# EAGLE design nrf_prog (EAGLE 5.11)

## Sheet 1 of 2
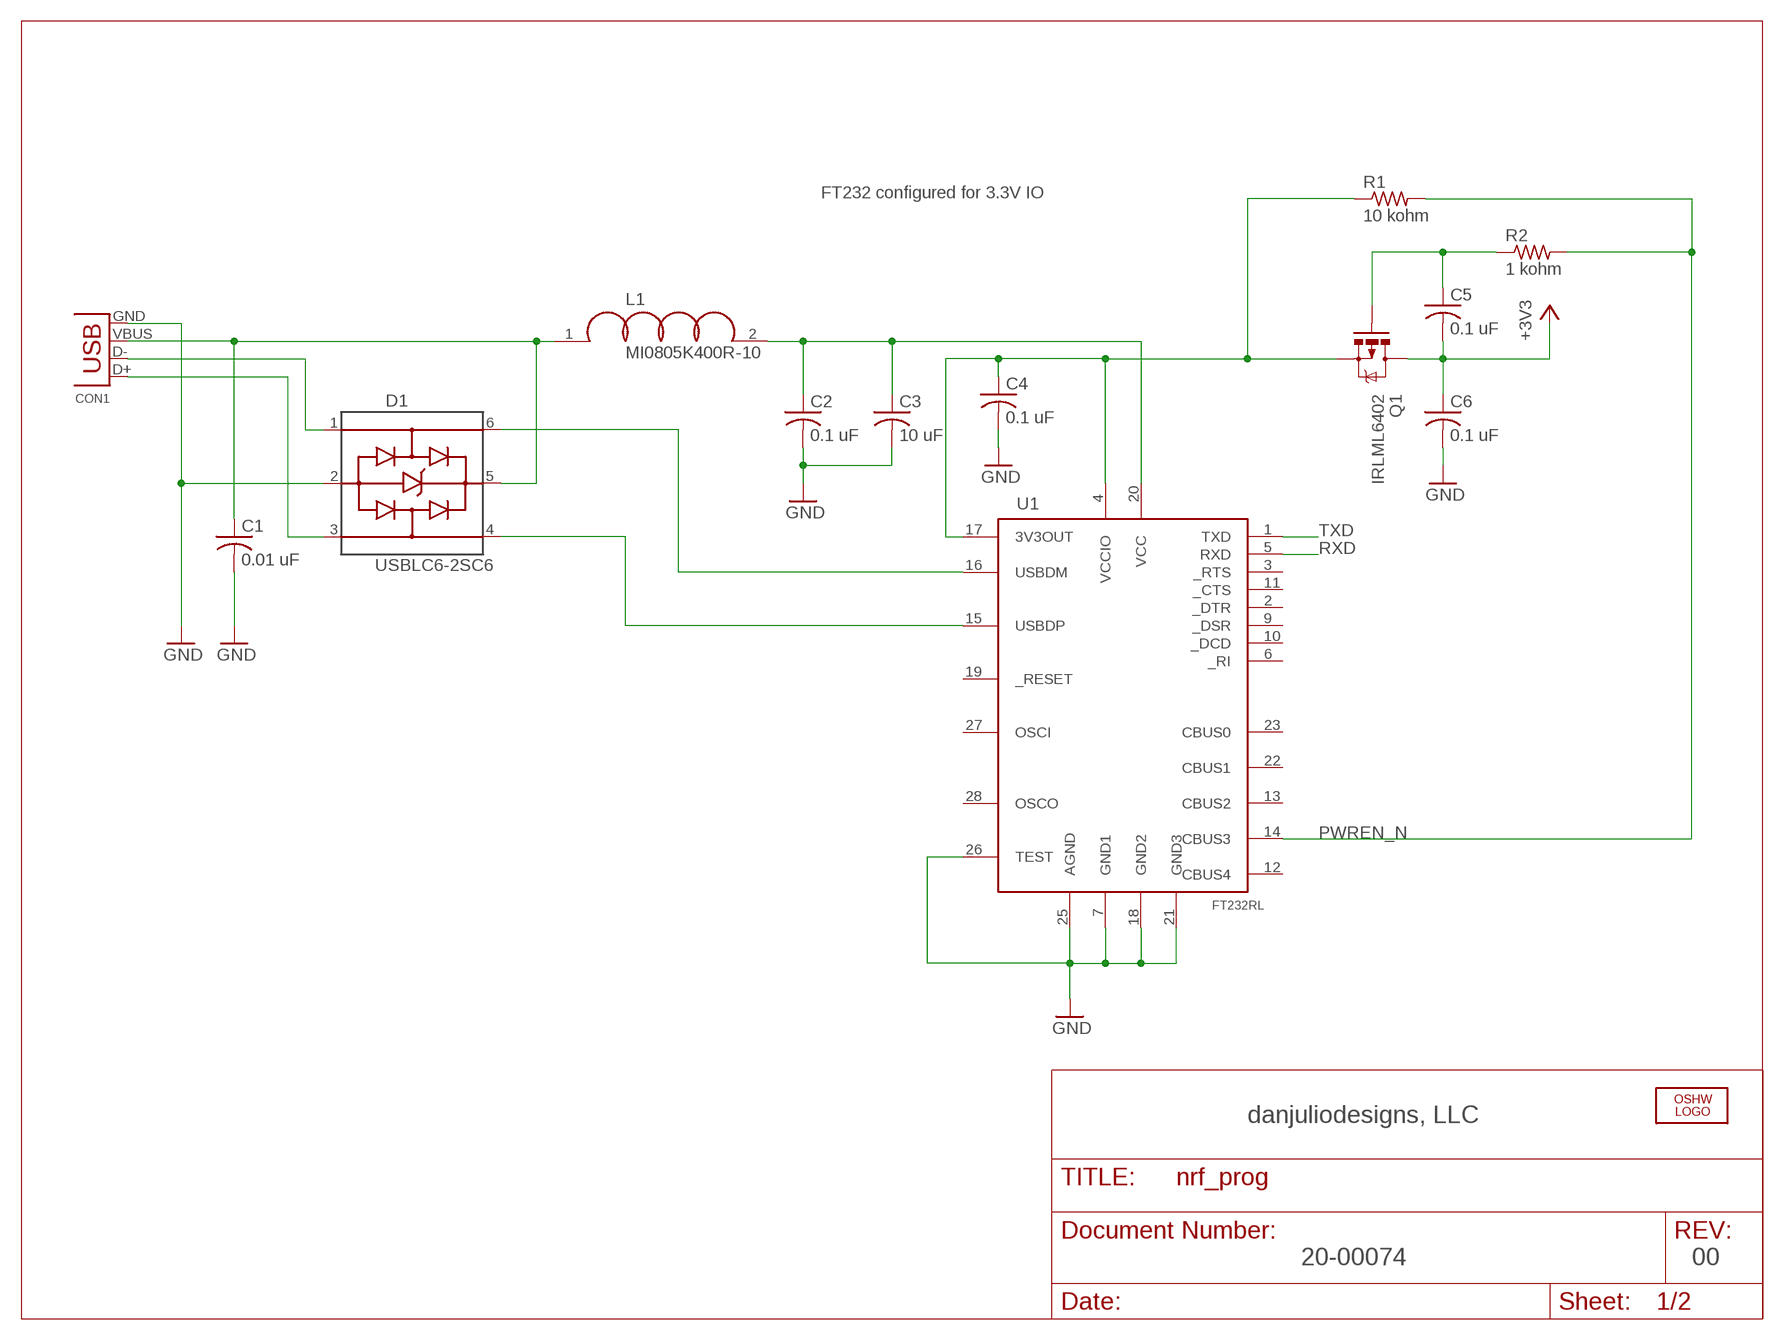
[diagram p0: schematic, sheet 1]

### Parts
C1  0.01 uF  C-USSMT0805  [C0805]
C2  0.1 uF  C-USSMT0805  [C0805]
C3  10 uF  C-USSMT1206  [C1206]
C4  0.1 uF  C-USSMT0805  [C0805]
C5  0.1 uF  C-USSMT0805  [C0805]
C6  0.1 uF  C-USSMT0805  [C0805]
CON1  USBMOLEX_675031020  [MOLEX_675031020]
D1  USBLC6-2SC6  USBLC6-2SOT23-6  [SOT23-6]
L1  MI0805K400R-10  INDUCTORSMT0805  [L0805]
LOGO1  OSHW_LOGO_FILLX0070-NT  [OSHW_FILLX70_NOTEXT]
Q1  IRLML6402  MOSFET-PCHANNEL  [SOT23-3]
R1  10 kohm  R-USSMT0805  [R0805]
R2  1 kohm  R-USSMT0805  [R0805]
U1  FT232RL  FT232RLSSOP28  [SSOP28DB]

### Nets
+3V3: C5.2 C6.1 Q1.3(D) ; also sheet 2
GND: C1.2 C2.2 C3.2 C4.2 C6.2 CON1.GND D1.2(GND) U1.7(GND1) U1.18(GND2) U1.21(GND3) U1.25(AGND) U1.26(TEST) ; also sheet 2
N$1: CON1.D- D1.1(IO1)
N$2: CON1.D+ D1.3(IO2)
N$3: C1.1 CON1.VBUS D1.5(VBUS) L1.1
N$4: C2.1 C3.1 L1.2 U1.20(VCC)
N$5: D1.6(IO1$1) U1.16(USBDM)
N$6: D1.4(IO2$1) U1.15(USBDP)
N$7: C4.1 Q1.2(S) R1.1 U1.4(VCCIO) U1.17(3V3OUT)
N$8: C5.1 Q1.1(G) R2.1
PWREN_N: R1.2 R2.2 U1.14(CBUS3)
RXD: U1.5(RXD) ; also sheet 2
TXD: U1.1(TXD) ; also sheet 2
Unconnected: U1.2(_DTR) U1.3(_RTS) U1.6(_RI) U1.9(_DSR) U1.10(_DCD) U1.11(_CTS) U1.12(CBUS4) U1.13(CBUS2) U1.19(_RESET) U1.22(CBUS1) U1.23(CBUS0) U1.27(OSCI) U1.28(OSCO)

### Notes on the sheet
- FT232 configured for 3.3V IO
- danjuliodesigns, LLC
- 20-00074 | 00

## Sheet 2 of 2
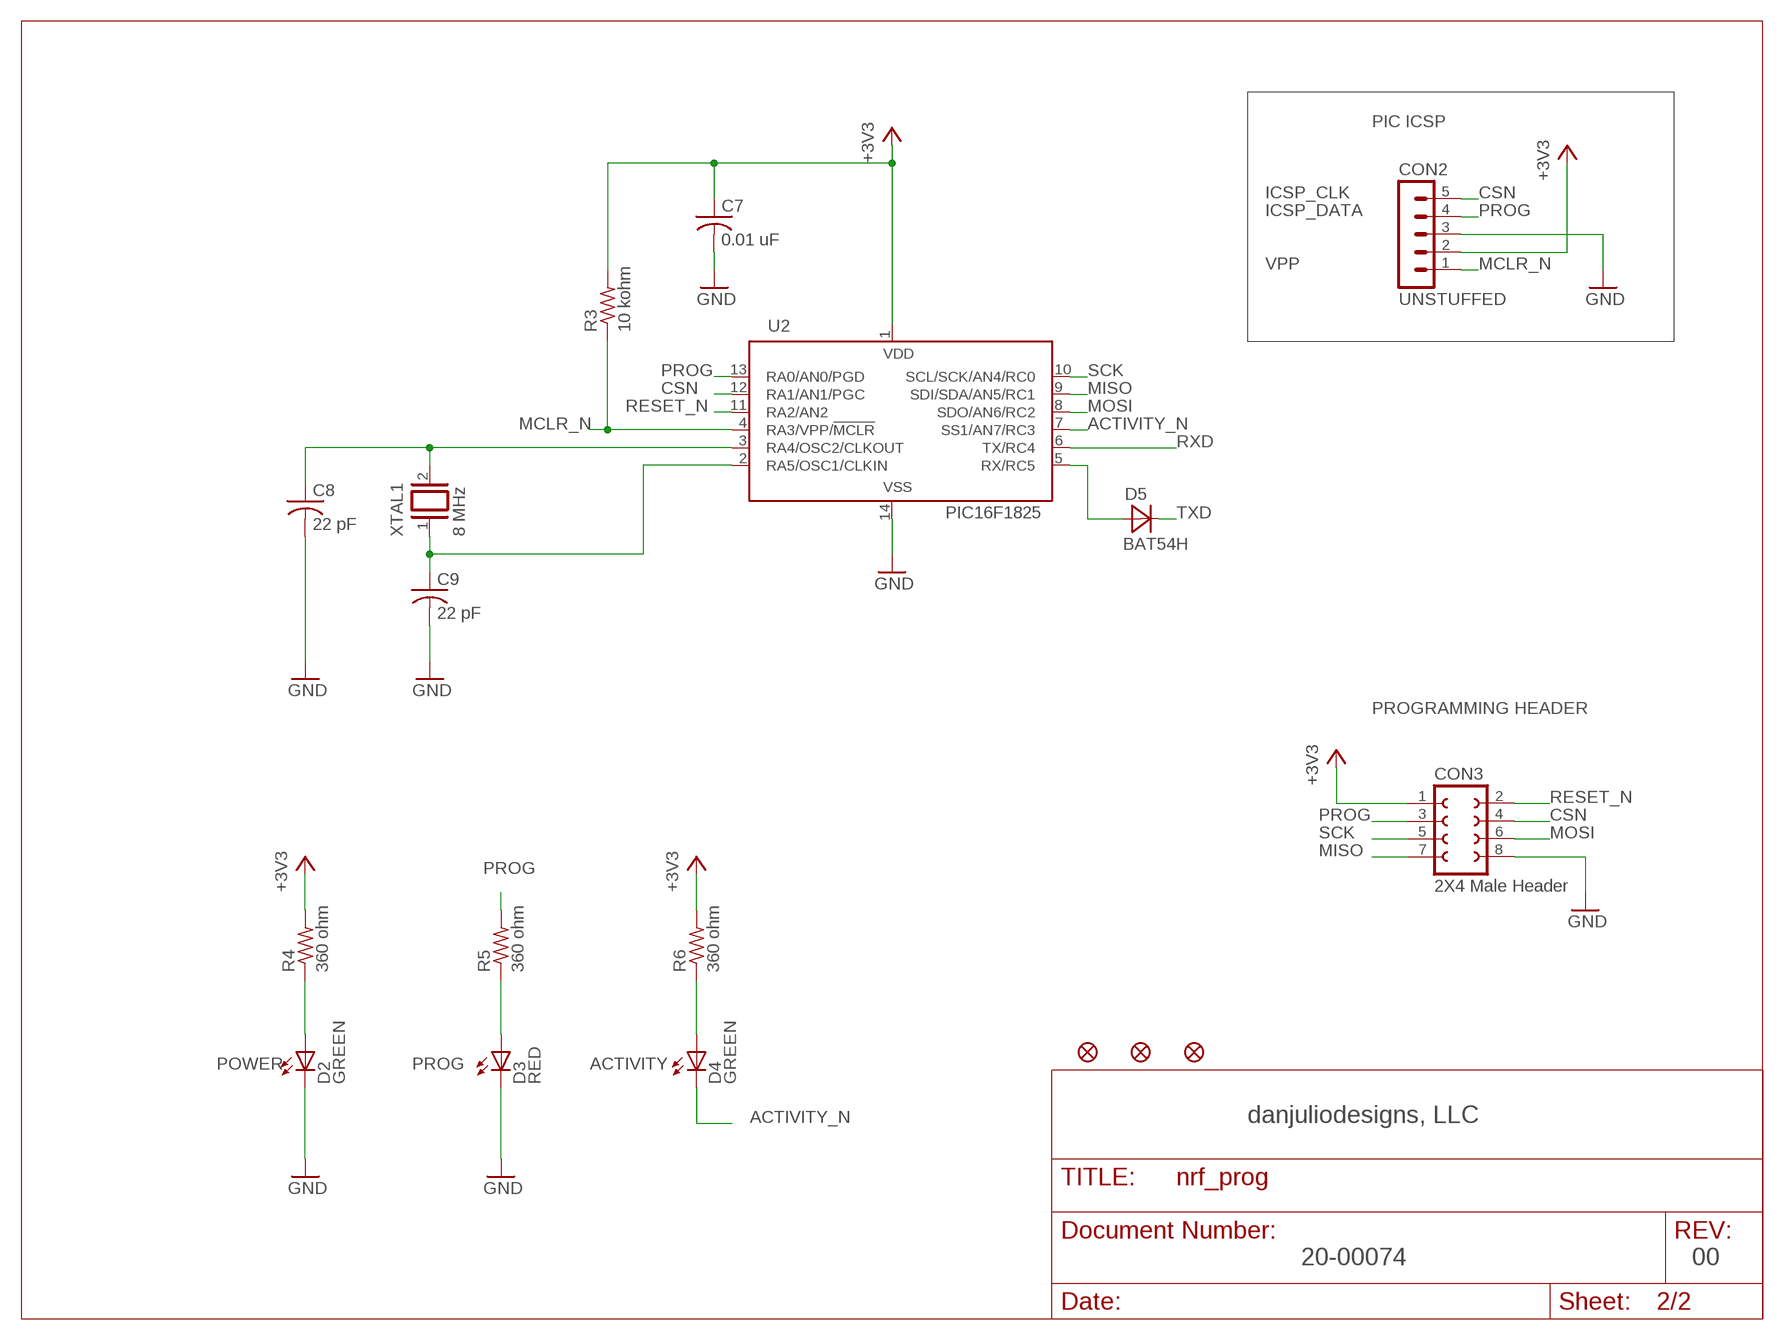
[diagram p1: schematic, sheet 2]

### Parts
C7  0.01 uF  C-USSMT0805  [C0805]
C8  22 pF  C-USSMT0805  [C0805]
C9  22 pF  C-USSMT0805  [C0805]
CON2  UNSTUFFED  MA05-1  [MA05-1]
CON3  2X4 Male Header  F_HDR_2_4TH  [F_HDR_2_4_TH]
D2  GREEN  LEDSMT0805  [LED_0805]
D3  RED  LEDSMT0805  [LED_0805]
D4  GREEN  LEDSMT0805  [LED_0805]
D5  BAT54H  DIODESMT_SOD123  [SOD123]
R3  10 kohm  R-USSMT0805  [R0805]
R4  360 ohm  R-USSMT0805  [R0805]
R5  360 ohm  R-USSMT0805  [R0805]
R6  360 ohm  R-USSMT0805  [R0805]
U2  PIC16F1825  PIC16F1825SO14  [SO14]
U$1  FIDUCIAL  [FIDUCIAL]
U$2  FIDUCIAL  [FIDUCIAL]
U$3  FIDUCIAL  [FIDUCIAL]
XTAL1  8 MHz  CRYSTALHC49_SMT  [HC49_US_SMT]

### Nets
+3V3: C7.1 CON2.2 CON3.1 R3.2 R4.2 R6.2 U2.1(VDD) ; also sheet 1
ACTIVITY_N: D4.C U2.7(SS1/AN7/RC3)
CSN: CON2.5 CON3.4 U2.12(RA1/AN1/PGC)
GND: C7.2 C8.2 C9.2 CON2.3 CON3.8 D2.C D3.C U2.14(VSS) ; also sheet 1
MCLR_N: CON2.1 R3.1 U2.4(RA3/VPP/!MCLR)
MISO: CON3.7 U2.9(SDI/SDA/AN5/RC1)
MOSI: CON3.6 U2.8(SDO/AN6/RC2)
N$9: C9.1 U2.2(RA5/OSC1/CLKIN) XTAL1.1
N$11: C8.1 U2.3(RA4/OSC2/CLKOUT) XTAL1.2
N$20: D5.A U2.5(RX/RC5)
N$23: D2.A R4.1
N$24: D3.A R5.1
N$26: D4.A R6.1
PROG: CON2.4 CON3.3 R5.2 U2.13(RA0/AN0/PGD)
RESET_N: CON3.2 U2.11(RA2/AN2)
RXD: U2.6(TX/RC4) ; also sheet 1
SCK: CON3.5 U2.10(SCL/SCK/AN4/RC0)
TXD: D5.C ; also sheet 1

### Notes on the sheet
- PIC ICSP
- ICSP_CLK
- ICSP_DATA
- VPP
- PROGRAMMING HEADER
- POWER | PROG | ACTIVITY
- danjuliodesigns, LLC
- 20-00074 | 00

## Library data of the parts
C1-C9 = djd_eagle_library:C-US
CON1 = djd_eagle_library:USB
CON2 = djd_eagle_library:MA05-1
CON3 = djd_eagle_library:F_HDR_2_4
D1 = djd_eagle_library:USBLC6-2
D2-D4 = djd_eagle_library:LED
D5 = djd_eagle_library:DIODE
L1 = djd_eagle_library:INDUCTOR
LOGO1 = ohw-logo:OSHW_LOGO_FILL
Q1 = djd_eagle_library:MOSFET-PCHANNEL
R1-R6 = djd_eagle_library:R-US
U1 = djd_eagle_library:FT232RL: USB UART FTDI FT232R USB interface
U2 = djd_eagle_library:PIC16F1825
U$1-U$3 = djd_eagle_library:FIDUCIAL
XTAL1 = djd_eagle_library:CRYSTAL

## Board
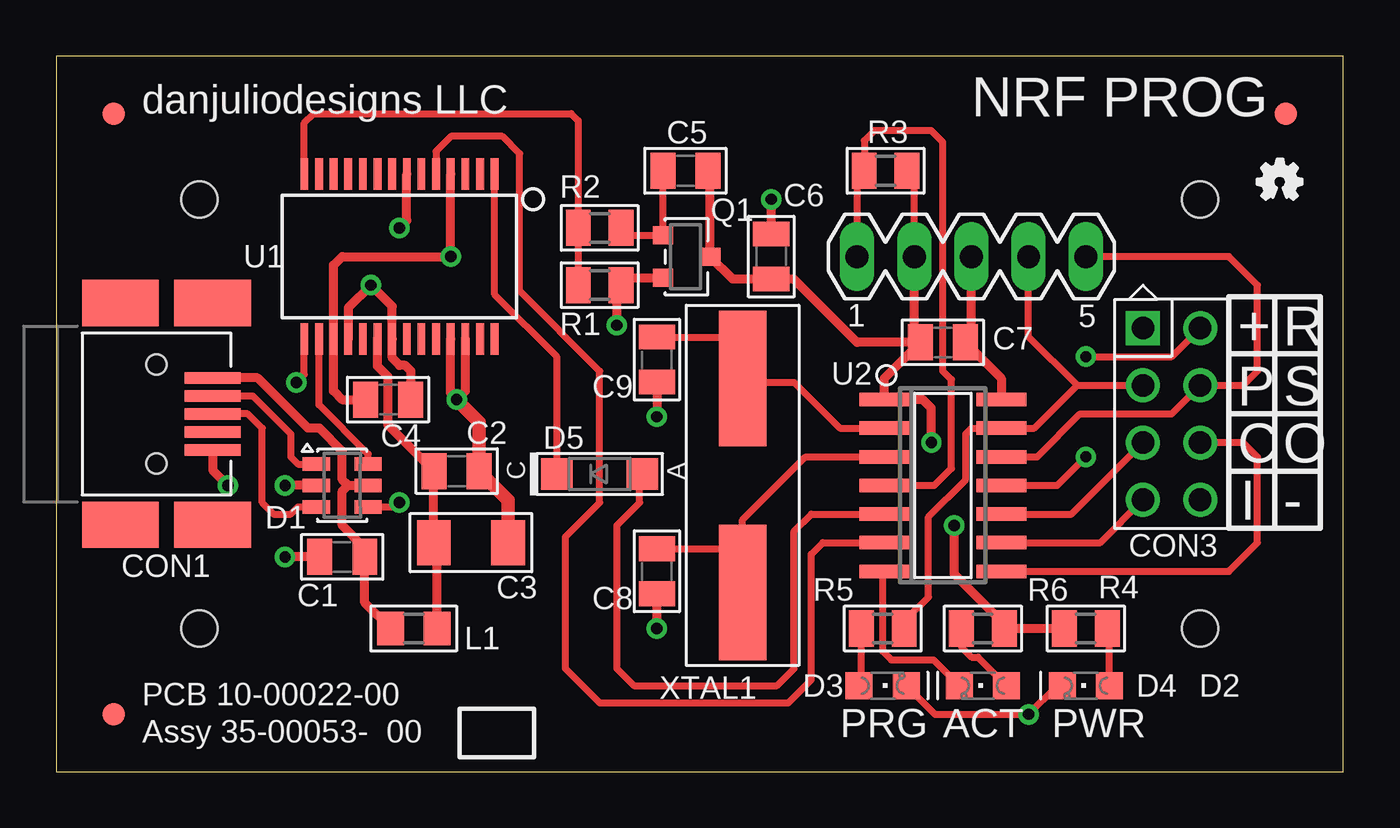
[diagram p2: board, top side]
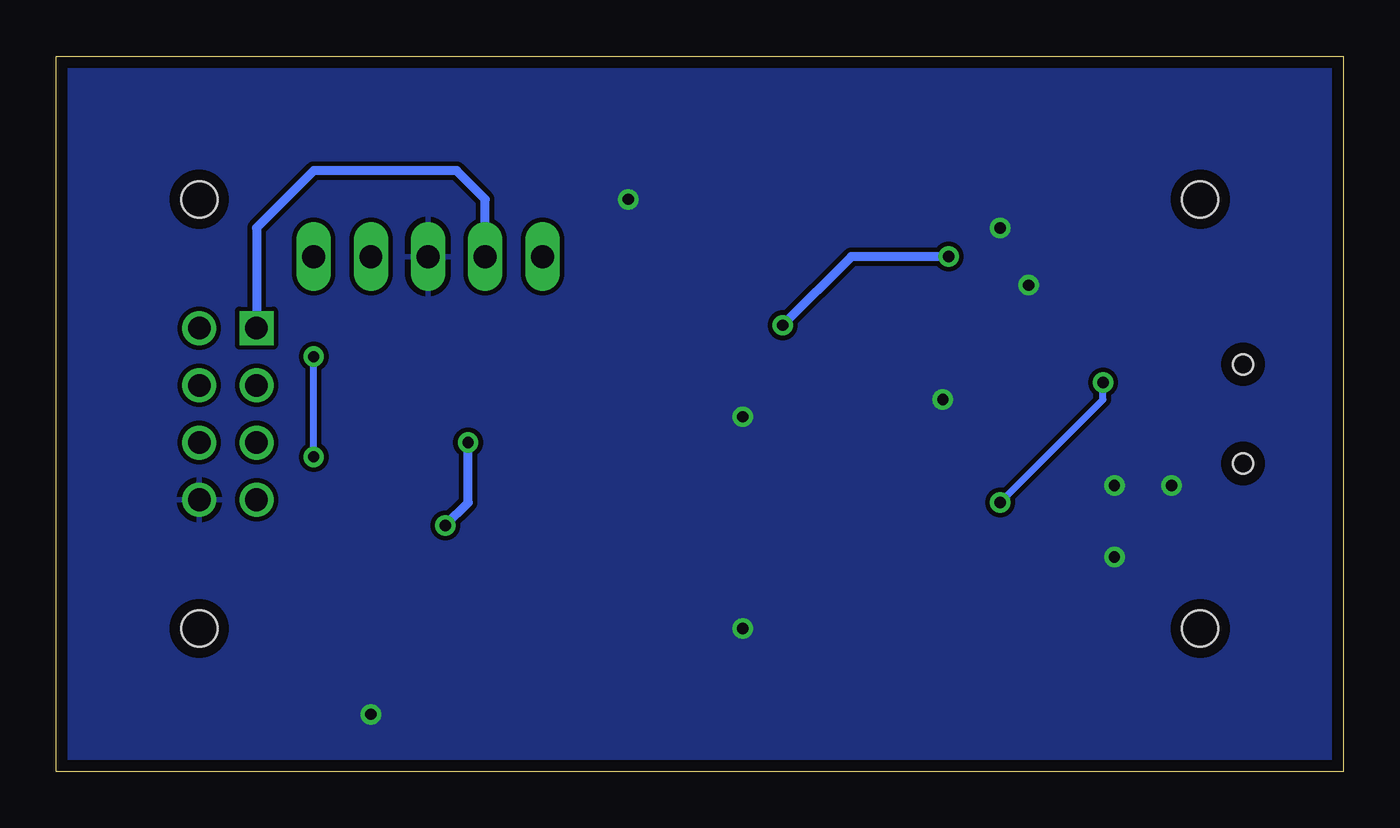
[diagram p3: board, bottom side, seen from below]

Size 57.15 x 31.75 mm. Coordinates in mm from the lower left corner, seen from the top.
Outline: 0,0 57.15,0 57.15,31.75 0,31.75 0,0
Copper layers (1*16): Top 0.035mm / dielectric 1.5mm / Bottom 0.035mm
Design rules "accutrace": minimum track width 7mil, minimum drill 15mil, track to track 8mil, track to pad 8mil, pad to pad 8mil, via to via 8mil, smd to smd 8mil, copper to edge 20mil, drill to drill 8mil, minimum pad ring 10mil, minimum via ring 8mil, stop-mask expansion 4mil, vias tented up to drill 0mil, thermal gap 10mil
Holes 1.6 mm at 6.35,6.35 6.35,25.4 50.8,25.4 50.8,6.35

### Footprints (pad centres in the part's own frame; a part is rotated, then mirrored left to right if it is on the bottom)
C0805 = smd 1.1 x 1.6: 1 -1,0; 2 1,0
C1206 = smd 2 x 1.5: 1 0,-1.65; 2 0,1.65
MOLEX_675031020 = smd 2.5 x 0.5: D+ 2.5,0; D- 2.5,0.8; GND 2.5,-1.6; ID 2.5,-0.8; VBUS 2.5,1.6 | smd 3.4 x 2.05: P$1 -1.6,-4.925; P$2 -1.6,4.925; P$3 2.5,-4.925; P$4 2.5,4.925 | hole 0.9: 0,2.2; 0,-2.2
MA05-1 = drill 1.016 long: 1 -5.08,0; 2 -2.54,0; 3 0,0; 4 2.54,0; 5 5.08,0
F_HDR_2_4_TH = drill 1 square: 1 -3.81,-1.27 | drill 1 round: 2 -3.81,1.27; 3 -1.27,-1.27; 4 -1.27,1.27; 5 1.27,-1.27; 6 1.27,1.27; 7 3.81,-1.27; 8 3.81,1.27
SOT23-6 = smd 0.6 x 1.2: 1 -0.95,-1.15; 2 0,-1.15; 3 0.95,-1.15; 4 0.95,1.15; 5 0,1.15; 6 -0.95,1.15
LED_0805 = smd 1.2 x 1.2: A 0,-1.05; C 0,1.05
SOD123 = smd 1.4 x 1.4: A 1.9,0; C -1.9,0
L0805 = smd 1.2 x 1.5: 1 -1.03,0; 2 1.03,0
SOT23-3 = smd 0.8 x 0.9: 1 -0.95,-1; 2 0.95,-1; 3 0,1.1
R0805 = smd 1.1 x 1.6: 1 -0.95,0; 2 0.95,0
SSOP28DB = smd 0.348 x 1.397: 1 -4.225,-3.656; 2 -3.575,-3.656; 3 -2.925,-3.656; 4 -2.275,-3.656; 5 -1.625,-3.656; 6 -0.975,-3.656; 7 -0.325,-3.656; 8 0.325,-3.656; 9 0.975,-3.656; 10 1.625,-3.656; 11 2.275,-3.656; 12 2.925,-3.656; 13 3.575,-3.656; 14 4.225,-3.656; 15 4.225,3.656; 16 3.575,3.656; 17 2.925,3.656; 18 2.275,3.656; 19 1.625,3.656; 20 0.975,3.656; 21 0.325,3.656; 22 -0.325,3.656; 23 -0.975,3.656; 24 -1.625,3.656; 25 -2.275,3.656; 26 -2.925,3.656; 27 -3.575,3.656; 28 -4.225,3.656
SO14 = smd 0.6 x 2.2: 1 -3.81,-2.6; 2 -2.54,-2.6; 3 -1.27,-2.6; 4 0,-2.6; 5 1.27,-2.6; 6 2.54,-2.6; 7 3.81,-2.6; 8 3.81,2.6; 9 2.54,2.6; 10 1.27,2.6; 11 0,2.6; 12 -1.27,2.6; 13 -2.54,2.6; 14 -3.81,2.6
FIDUCIAL = smd 1 x 1: 1 0,0
HC49_US_SMT = smd 6 x 2.1: 1 -4.75,0; 2 4.75,0

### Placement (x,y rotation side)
C1  12.7,9.53 180 top
C2  17.78,13.34 0 top
C3  18.41,10.16 270 top
C4  14.73,16.51 0 top
C5  27.94,26.67 0 top
C6  31.75,22.86 90 top
C7  39.37,19.05 0 top
C8  26.67,8.89 270 top
C9  26.67,18.29 270 top
CON1  4.45,15.88 0 top
CON2  40.64,22.86 0 top
CON3  49.53,15.88 270 top
D1  12.7,12.7 270 top
D2  45.72,3.81 90 top
D3  36.7,3.81 270 top
D4  41.15,3.81 90 top
D5  24.13,13.21 0 top
L1  15.88,6.35 0 top
LOGO1  53.34,25.4 0 top
Q1  27.94,22.86 270 top
R1  24.13,21.59 180 top
R2  24.13,24.13 180 top
R3  36.83,26.67 0 top
R4  45.72,6.35 180 top
R5  36.7,6.35 0 top
R6  41.15,6.35 0 top
U1  15.24,22.86 180 top
U2  39.37,12.7 270 top
U$1  2.54,29.21 0 top
U$2  2.54,2.54 0 top
U$3  54.61,29.21 0 top
XTAL1  30.48,12.7 270 top

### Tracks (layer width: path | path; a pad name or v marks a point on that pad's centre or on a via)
+3V3  (via drill 0.5)
  Top 0.305: CON2.2 38.1,26.35 R3.2
  Top 0.406: C5.2 29.04,26.57 Q1.3 30.04,21.86 C6.1 32.75,21.86 35.56,19.05 C7.1 | C7.1 36.77,17.45 U2.1 38.48,16.51 38.86,16.13 v38.86,14.61 | CON2.2 38.1,19.32 C7.1 | R4.2 R6.2 42.1,6.54 39.88,8.76 v39.88,10.92
  Bottom 0.406: CON2.2 38.1,25.4 39.37,26.67 45.72,26.67 48.26,24.13 CON3.1 | v38.86,14.61 38.86,11.94 v39.88,10.92
ACTIVITY_N
  Top 0.305: U2.7 36.77,8.83 36.7,8.76 36.7,5.33 37.08,4.95 38.95,4.95 D4.C
CSN
  Top 0.305: CON2.5 52.07,22.86 53.34,21.59 53.34,17.78 52.7,17.14 CON3.4 49.53,15.88 45.47,15.88 43.56,13.97 U2.12
GND  (via drill 0.5)
  Top 0.305: D2.C 44.45,3.81 v43.18,2.54 39.02,2.54 D3.C
  Top 0.406: D1.2 v10.16,12.7 | CON1.GND 6.95,13.38 v7.62,12.7 | U1.7 15.56,24.45 v15.24,24.13 | U1.18 12.96,20.59 v13.97,21.59 14.91,20.64 U1.21 14.91,18.36 15.24,18.03 15.49,18.03 15.75,17.78 15.75,16.53 C4.2 | U1.25 17.52,16.77 v17.78,16.51 18.16,16.89 U1.26 | v26.67,6.35 C8.2 | C9.2 v26.67,15.75 | C6.2 v31.75,25.4 | CON2.3 40.64,19.32 C7.2 41.97,17.45 U2.14 | C1.2 v10.16,9.53
  Top 0.61: C3.2 20.07,12.05 C2.2 18.78,15.51 v17.78,16.51
  pour Bottom: 0,31.75 0,0 57.15,0 57.15,31.75
MCLR_N
  Top 0.305: U2.4 38.99,12.7 39.75,13.46 39.75,17.4 39.37,17.78 39.37,27.94 38.86,28.45 36.32,28.45 35.88,28.01 R3.1 35.56,26.35 CON2.1
MISO
  Top 0.305: U2.9 46.35,10.16 CON3.7
MOSI
  Top 0.305: U2.8 52.07,8.89 53.34,10.16 53.34,13.97 52.7,14.61 CON3.6
N$1
  Top 0.305: CON1.D- 8.72,16.68 10.41,14.99 10.41,13.97 10.73,13.65 D1.1
N$2
  Top 0.305: D1.3 10.73,11.75 10.41,11.43 9.65,11.43 9.14,11.94 9.14,15.24 8.51,15.88 CON1.D+
N$3
  Top 0.406: 12.95,12.7 D1.5 | 12.95,12.7 12.7,12.95 12.7,14.22 11.68,15.24 11.18,15.24 8.94,17.48 CON1.VBUS | 12.95,12.7 12.7,12.45 12.7,10.92 13.7,9.92 C1.1 13.7,7.5 L1.1
N$4
  Top 0.406: L1.2 16.91,10.02 C3.1 16.77,13.32 C2.1 14.73,15.38 14.73,17.53 14.27,17.99 U1.20
N$5
  Top 0.305: D1.6 13.85,14.09 11.66,16.27 U1.16
N$6  (via drill 0.5)
  Top 0.305: U1.15 11.02,17.62 v10.67,17.27 | D1.4 15.05,11.75 v15.24,11.94
  Bottom 0.305: v10.67,17.27 10.67,16.51 v15.24,11.94
N$7  (via drill 0.5)
  Top 0.406: C4.1 12.7,16.51 12.31,16.89 U1.17 12.31,22.48 12.7,22.86 v17.53,22.86 17.52,22.87 U1.4 | Q1.2 25.4,21.91 R1.1 24.89,21.4 v24.89,19.81
  Bottom 0.406: v17.53,22.86 21.84,22.86 v24.89,19.81
N$8
  Top 0.305: R2.1 25.4,23.81 Q1.1 C5.1
N$9
  Top 0.305: U2.2 34.8,15.24 32.77,17.27 30.66,17.27 XTAL1.1 30.48,19.05 30.24,19.29 C9.1
N$11
  Top 0.305: 30.48,9.65 XTAL1.2 | 30.48,9.65 30.48,11.18 33.27,13.97 U2.3 | C8.1 30.24,9.89 30.48,9.65
N$20
  Top 0.305: U2.5 33.53,11.43 32.77,10.67 32.77,4.57 32,3.81 25.65,3.81 24.89,4.57 24.89,10.92 25.91,11.94 25.91,13.09 D5.A
N$23
  Top 0.305: D2.A 46.77,6.25 R4.1
N$24
  Top 0.305: R5.1 35.75,3.91 D3.A
N$26
  Top 0.305: R6.1 40.2,5.52 40.64,5.08 40.93,5.08 D4.A
PROG
  Top 0.305: 45.34,17.14 43.43,15.24 U2.13 40.64,15.24 40.39,14.99 40.39,12.95 38.73,11.3 38.73,7.75 37.65,6.67 R5.2 | CON2.4 43.18,19.3 45.34,17.14 | 45.34,17.14 CON3.3
PWREN_N
  Top 0.305: R1.2 R2.2 23.18,28.89 22.86,29.21 11.43,29.21 11.02,28.8 U1.14
RESET_N  (via drill 0.5)
  Top 0.305: U2.11 44.45,12.7 v45.72,13.97 | v45.72,18.41 49.53,18.41 CON3.2
  Bottom 0.305: v45.72,13.97 v45.72,18.41
RXD
  Top 0.305: U1.5 16.86,27.53 17.53,28.19 19.81,28.19 20.57,27.43 20.57,21.34 24.13,17.78 24.13,11.94 22.61,10.41 22.61,4.57 24.13,3.05 32.51,3.05 33.53,4.06 33.53,9.65 34.04,10.16 U2.6
SCK
  Top 0.305: U2.10 45.09,11.43 CON3.5
TXD
  Top 0.305: U1.1 19.46,21.18 22.23,18.41 D5.C

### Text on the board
tNames: danjuliodesigns LLC | NRF PROG | + | R | P | S | C | O | I | - | PCB 10-00022-00 | PRG | ACT | PWR | Assy 35-00053- 00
